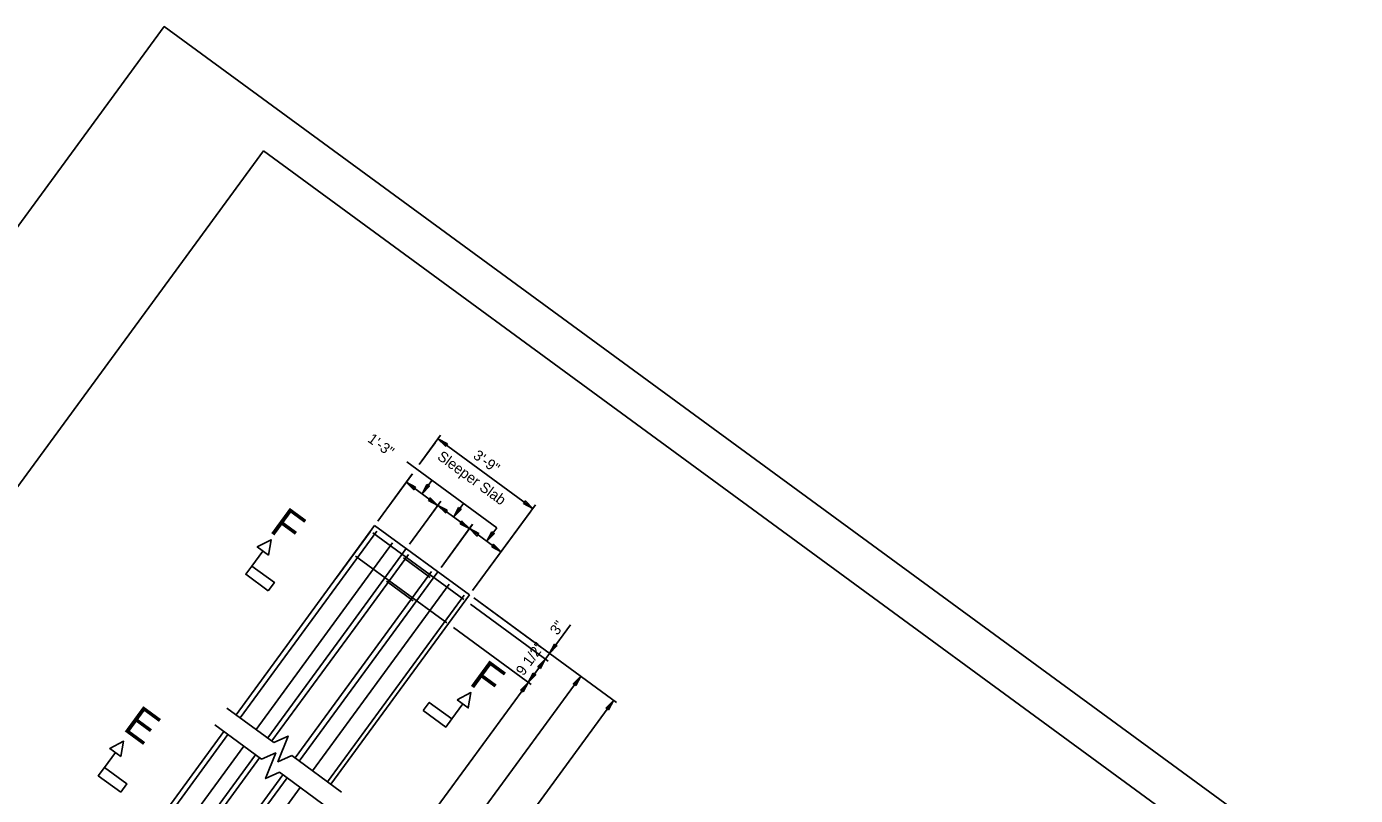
# Model space of a CAD drawing. Extents: x 1970654 to 1970899, y 796145 to 796378.
# Drawn here: x 1970776.7 to 1970840.2, y 796264.5 to 796301.3 of the extents above; entities that cross this region are included whole.
import ezdxf

# ---------------------------------------------------------------- set-up
doc = ezdxf.new("R2010")
doc.units = 0
for name, color, linetype in [('BR_AUTO DIMENSION', 7, 'Continuous'), ('BR_BORDER LINES', 7, 'Continuous'), ('BR_CONCRETE', 7, 'Continuous'), ('BR_REBAR', 7, 'Continuous'), ('BR_TABLE LINES', 7, 'Continuous'), ('BR_TEXT', 7, 'Continuous'), ('Level 31', 7, 'Continuous')]:
    doc.layers.add(name, color=color, linetype=linetype)

msp = doc.modelspace()

# ---------------------------------------------------------------- linework, layer by layer
at = {"layer": 'BR_AUTO DIMENSION'}
for p, q in [((1970795.429, 796280.341), (1970796.193, 796281.386)), ((1970795.432, 796280.346), (1970796.455, 796281.744)), ((1970800.871, 796278.253), (1970796.332, 796281.575)), ((1970794.837, 796280.471), (1970799.142, 796277.319)), ((1970793.451, 796277.64), (1970795.085, 796279.872)), ((1970793.931, 796278.296), (1970795.111, 796279.907)), ((1970794.813, 796279.5), (1970796.325, 796278.392)), ((1970795.569, 796278.946), (1970796.04, 796279.59)), ((1970794.964, 796276.532), (1970796.37, 796278.453)), ((1970795.716, 796277.559), (1970796.473, 796278.594)), ((1970795.716, 796277.559), (1970796.473, 796278.594)), ((1970796.325, 796278.392), (1970797.838, 796277.285)), ((1970797.082, 796277.839), (1970797.553, 796278.482)), ((1970797.989, 796274.317), (1970800.994, 796278.421)), ((1970797.989, 796274.317), (1970800.732, 796278.063)), ((1970796.477, 796275.425), (1970797.99, 796277.492)), ((1970796.477, 796275.425), (1970797.986, 796277.486)), ((1970796.477, 796275.425), (1970797.986, 796277.486)), ((1970797.838, 796277.285), (1970799.351, 796276.177)), ((1970798.67, 796276.676), (1970799.142, 796277.319)), ((1970797.888, 796273.665), (1970801.599, 796270.948)), ((1970798.044, 796273.968), (1970804.864, 796268.974)), ((1970798.044, 796273.968), (1970801.293, 796271.589)), ((1970798.044, 796273.968), (1970801.293, 796271.589)), ((1970802.667, 796272.689), (1970768.229, 796225.652)), ((1970797.072, 796272.549), (1970800.782, 796269.833)), ((1970803.156, 796270.225), (1970770.665, 796225.847)), ((1970772.237, 796224.696), (1970804.728, 796269.074)), ((1970788.481, 796267.065), (1970786.242, 796268.704)), ((1970787.893, 796266.262), (1970785.654, 796267.901)), ((1970791.724, 796264.691), (1970789.339, 796266.437)), ((1970791.136, 796263.888), (1970788.752, 796265.634))]:
    msp.add_line(p, q, dxfattribs=at)
for points in [[(1970796.78, 796281.341), (1970796.332, 796281.575), (1970796.691, 796281.22)], [(1970795.26, 796279.265), (1970794.813, 796279.5), (1970795.172, 796279.144)], [(1970795.804, 796279.394), (1970795.569, 796278.946), (1970795.925, 796279.305)], [(1970795.878, 796278.627), (1970796.325, 796278.392), (1970795.966, 796278.748)], [(1970796.773, 796278.158), (1970796.325, 796278.392), (1970796.685, 796278.036)], [(1970797.317, 796278.286), (1970797.082, 796277.839), (1970797.438, 796278.198)], [(1970800.423, 796278.487), (1970800.871, 796278.253), (1970800.512, 796278.608)], [(1970797.391, 796277.52), (1970797.838, 796277.285), (1970797.479, 796277.641)], [(1970798.286, 796277.05), (1970797.838, 796277.285), (1970798.197, 796276.929)], [(1970798.905, 796277.123), (1970798.67, 796276.676), (1970799.026, 796277.035)], [(1970798.903, 796276.412), (1970799.351, 796276.177), (1970798.992, 796276.533)], [(1970801.898, 796271.766), (1970801.663, 796271.318), (1970802.019, 796271.677)], [(1970801.23, 796270.599), (1970801.464, 796271.047), (1970801.109, 796270.688)], [(1970800.413, 796269.483), (1970800.648, 796269.931), (1970800.292, 796269.572)], [(1970800.882, 796270.379), (1970800.648, 796269.931), (1970801.003, 796270.29)], [(1970802.921, 796269.777), (1970803.156, 796270.225), (1970802.8, 796269.866)], [(1970804.493, 796268.626), (1970804.728, 796269.074), (1970804.372, 796268.715)]]:
    msp.add_lwpolyline(points, close=True, dxfattribs=at)
for points in [[(1970788.481, 796267.065), (1970789.161, 796267.366), (1970788.675, 796266.14), (1970789.339, 796266.437)], [(1970787.893, 796266.262), (1970788.573, 796266.563), (1970788.087, 796265.337), (1970788.752, 796265.634)]]:
    msp.add_lwpolyline(points, dxfattribs=at)
at = {"layer": 'BR_BORDER LINES'}
for p in [(1970738.359, 796227.562), (1970896.636, 796215.787)]:
    msp.add_line(p, (1970787.981, 796295.338), dxfattribs=at)
at = {"layer": 'BR_CONCRETE'}
for p, q in [((1970786.676, 796268.387), (1970793.303, 796277.438)), ((1970797.842, 796274.115), (1970793.303, 796277.438)), ((1970791.457, 796274.917), (1970793.082, 796277.136)), ((1970792.158, 796272.7), (1970794.816, 796276.331)), ((1970789.702, 796266.171), (1970796.329, 796275.223)), ((1970791.215, 796265.064), (1970797.842, 796274.115)), ((1970788.189, 796267.279), (1970792.158, 796272.7)), ((1970771.606, 796247.804), (1970786.088, 796267.584)), ((1970773.119, 796246.696), (1970787.601, 796266.476)), ((1970774.632, 796245.588), (1970789.114, 796265.368))]:
    msp.add_line(p, q, dxfattribs=at)
at = {"layer": 'BR_REBAR'}
for p, q in [((1970786.878, 796268.239), (1970793.408, 796277.159)), ((1970793.212, 796277.089), (1970797.572, 796273.897)), ((1970787.634, 796267.685), (1970794.165, 796276.605)), ((1970792.367, 796272.562), (1970794.921, 796276.051)), ((1970792.395, 796275.973), (1970796.755, 796272.781)), ((1970794.681, 796275.885), (1970795.957, 796274.95)), ((1970789.498, 796266.321), (1970796.029, 796275.24)), ((1970790.332, 796265.71), (1970796.863, 796274.63)), ((1970793.864, 796274.769), (1970795.14, 796273.835)), ((1970791.057, 796265.179), (1970797.587, 796274.099)), ((1970788.391, 796267.131), (1970792.367, 796272.562)), ((1970781.449, 796260.823), (1970786.29, 796267.436)), ((1970778.016, 796254.548), (1970787.046, 796266.882)), ((1970773.321, 796246.548), (1970787.803, 796266.328)), ((1970774.428, 796245.737), (1970788.91, 796265.517)), ((1970775.262, 796245.127), (1970789.744, 796264.907))]:
    msp.add_line(p, q, dxfattribs=at)
at = {"layer": 'BR_TABLE LINES'}
for p, q in [((1970787.432, 796275.495), (1970787.957, 796276.212)), ((1970796.989, 796268.189), (1970797.514, 796268.906)), ((1970780.38, 796265.863), (1970780.905, 796266.58))]:
    msp.add_line(p, q, dxfattribs=at)
for points in [[(1970788.226, 796276.016), (1970788.351, 796276.75), (1970787.688, 796276.409)], [(1970788.219, 796274.313), (1970788.508, 796274.708), (1970787.432, 796275.495), (1970787.143, 796275.101)], [(1970797.245, 796269.103), (1970797.908, 796269.444), (1970797.783, 796268.709)], [(1970795.624, 796268.582), (1970795.913, 796268.976), (1970796.989, 796268.189), (1970796.7, 796267.794)], [(1970781.174, 796266.383), (1970781.299, 796267.118), (1970780.636, 796266.777)], [(1970781.167, 796264.681), (1970781.456, 796265.075), (1970780.38, 796265.863), (1970780.091, 796265.468)]]:
    msp.add_lwpolyline(points, close=True, dxfattribs=at)
at = {"layer": 'Level 31'}
msp.add_lwpolyline([(1970731.261, 796230.28), (1970847.449, 796145.214), (1970899.434, 796216.218), (1970783.245, 796301.284)], close=True, dxfattribs=at)

# ---------------------------------------------------------------- texts
at = {"layer": 'BR_AUTO DIMENSION'}
for s, rotation, p in [('3\'-9"', 323.79058, (1970797.973, 796280.684)), ('3"', 53.79058, (1970802.045, 796272.154)), ('9 1/2"', 53.79058, (1970800.417, 796270.216))]:
    msp.add_text(s, height=0.5, rotation=rotation, dxfattribs=at).set_placement(p)
at = {"layer": 'BR_TEXT'}
for s, height, p in [('1\'-3"', 0.4999, (1970792.926, 796281.473)), ('Sleeper Slab', 0.49995, (1970796.259, 796280.636)), ('F', 1.5, (1970788.226, 796277.164)), ('F', 1.5, (1970797.774, 796269.864)), ('E', 1.5, (1970781.222, 796267.684))]:
    msp.add_text(s, height=height, rotation=323.79058, dxfattribs=at).set_placement(p)

doc.saveas('drawing.dxf')
